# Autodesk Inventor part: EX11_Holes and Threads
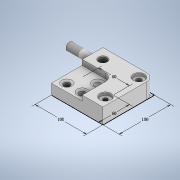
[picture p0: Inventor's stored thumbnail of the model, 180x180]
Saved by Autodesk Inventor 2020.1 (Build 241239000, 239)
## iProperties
Created: 2019-10
Part Number: EX11_Holes and Threads
Material: Generic
Document SubType Name: Modeling
Designer: Synergysoft Dell02
Density: 1 g/cm^3
Appearance: Default
Author: Synergysoft Dell02
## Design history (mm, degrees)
sketch "Sketch1"
  geometry: L1 (50, -50)-(-50, -50); L2 (-50, -50)-(-50, 50); L3 (-50, 50)-(50, 50); L4 (50, 50)-(50, -50); L5 (50, -50)-(-50, 50); L6 (-50, -50)-(50, 50); L7 (50, 50)-(-10, 50); L8 (-10, 50)-(-10, -10); L9 (-10, -10)-(50, -10); L10 (50, -10)-(50, 50); 3 further points
  constraints: 20 end point, 4 parallel, 2 horizontal, 2 midpoint, 2 perpendicular
  dimensions: "d0" = 100 distance of L2.end L3.end; "d1" = 100 distance of L1.end L2.end; "d2" = 60 distance of L9.end L8.end; "d3" = 60 distance of L8.end L7.end
extrude "Extrusion1" new body sketch "Sketch1" distance "d4" = 30; taper "d5" = 0 deg
extrude "Extrusion2" join sketch "Sketch1" distance "d6" = 20; taper "d7" = 0 deg
sketch "Sketch2"
  geometry: L1 (0, 0)-(0, 30) reference; L2 (0, 0)-(100, 0) reference; C1 r 7.5 at (15, 15); 1 further point
  constraints: 1 centre point
  dimensions: "d8" = 15 diameter of C1; "d9" = 15 distance from line of C1.centre L1; "d10" = 15 distance from line of L2 C1.centre
extrude "Extrusion3" join sketch "Sketch2" distance "d11" = 50; taper "d12" = 0 deg
fillet "Fillet1" dims "d13" = 15
sketch "Sketch3"
  geometry: L1 (-50, 50)-(-50, 10) reference; L2 (35, 50)-(-50, 50) reference; 2 further points
  dimensions: "d14" = 20 distance from line of L1 point (-30, 30); "d15" = 20 distance from line of L2 point (-30, 30)
hole "Hole1" sketch "Sketch3" at (-30, 30) diameter "d16" = 15; stored, may be unused: countersink angle "d20" = 90 deg, drill point angle "d22" = 118 deg; dims "d17" = 6, "d18" = 4, "d19" = 2, "d21" = 20
sketch "Sketch4"
  geometry: A1 r 15 centre (35, 35) between (50, 35) and (35, 50) reference; 2 further points
  constraints: 1 coincident
hole "Hole2" sketch "Sketch4" at (35, 35) diameter "d23" = 10; stored, may be unused: countersink angle "d27" = 90 deg, drill point angle "d29" = 118 deg; dims "d24" = 6, "d25" = 20, "d26" = 5, "d28" = 20
sketch "Sketch5"
  geometry: L1 (-50, 10)-(10, 10) reference; L2 (10, 10)-(10, -50) reference; L3 (-50, -50)-(10, -50) reference; L4 (-50, 10)-(-50, -50) reference; 4 further points
  dimensions: "d30" = 15 distance from line of L1 point (-5, -5); "d31" = 15 distance from line of L2 point (-5, -5); "d32" = 15 distance from line of L2 point (-5, -35); "d33" = 15 distance from line of L3 point (-5, -35); "d34" = 15 distance from line of L4 point (-35, -35); "d35" = 15 distance from line of L3 point (-35, -35)
hole "Hole3" sketch "Sketch5" at (-5, -5), (-5, -35), (-35, -35) diameter "d36" = 12; stored, may be unused: countersink angle "d40" = 118 deg, drill point angle "d42" = 118 deg; dims "d37" = 6, "d38" = 20, "d39" = 5, "d41" = 20
sketch "Sketch6"
  geometry: L1 (50, -50)-(50, 35) reference; L2 (10, -50)-(50, -50) reference; 2 further points
  dimensions: "d50" = 15 distance from line of L1 point (35, -30); "d51" = 20 distance from line of L2 point (35, -30)
hole "Hole4" sketch "Sketch6" at (35, -30) diameter "d43" = 8.376; stored, may be unused: countersink angle "d47" = 118 deg, drill point angle "d49" = 118 deg; dims "d44" = 15, "d45" = 20, "d46" = 5, "d48" = 27.3
thread "Thread1" dims "d52" = 20, "d53" = 0
thread "Thread2" dims "d54" = 25, "d55" = 25
chamfer "Chamfer1" distance "d56" = 1; stored, may be unused: second distance "d57" = 2, angle "d58" = 45 deg
fillet "Fillet2" dims "d59" = 15
body "Solid1"
